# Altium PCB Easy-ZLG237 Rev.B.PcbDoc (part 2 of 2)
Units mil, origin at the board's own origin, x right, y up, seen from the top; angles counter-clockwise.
Board outline 3937.01 x 2559.06 mil, 2 copper layers (Top Layer, Bottom Layer); 111 components, 102 nets, 447 pads, 498 vias.
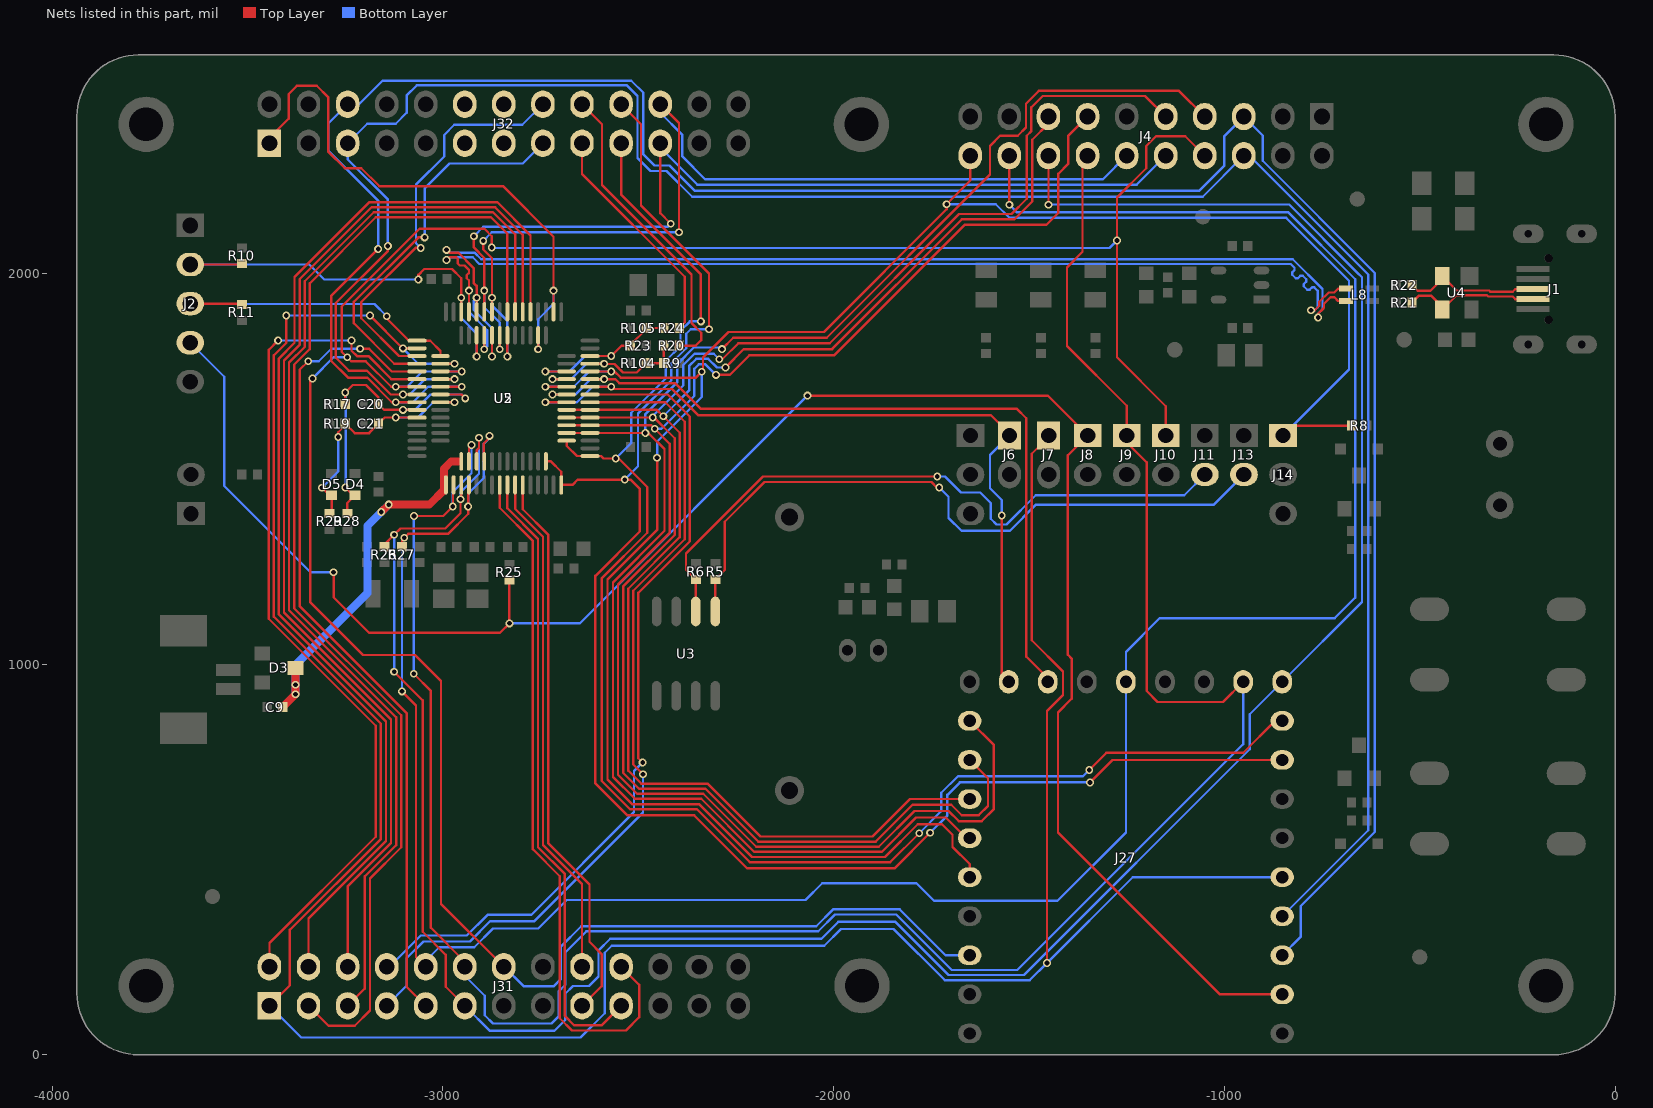
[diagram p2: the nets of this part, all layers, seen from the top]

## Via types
v1: diameter 20, hole 12, Top Layer to Bottom Layer, tented both sides, 498 vias

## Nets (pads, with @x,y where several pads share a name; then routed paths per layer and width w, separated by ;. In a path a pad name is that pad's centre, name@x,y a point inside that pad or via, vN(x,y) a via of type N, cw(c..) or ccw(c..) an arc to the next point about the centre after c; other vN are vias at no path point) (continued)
PA15_1: J7.1 J27.5 J31.1 U2.38 U5.50 | length 6978.5
  Top Layer w6: J31.1@-3444.17,125.15 -3392,177.32 -3392,319.54 -3159,552.54 -3159,847.38 -3433,1121.38 -3433,1790 -3401,1822 v1(-3401,1892) ; v1(-3187,1892) -3102.95,1807.95 U5.50@-3066.46,1807.95 ; U2.38@-3006.42,1768.58 v1(-2970.43,1768.58) ; v1(-1454,235) -1454,880 -1413,921 -1413,981 -1493,1061 -1493,1538 -1450,1581 J7.1@-1450,1585
  Bottom Layer w6: J31.1@-3444.17,125.15 -3363.01,44 -2648,44 -2586,106 -2586,261 -2568,279 -2024,279 -1981,322 -1847,322 -1716,191 -1498,191 v1(-1454,235) -1234.52,454.48 J27.5@-852,454.48 ; v1(-3401,1892) v1(-3187,1892) ; v1(-3102.45,1807.95) -3063.08,1768.58 v1(-2970.43,1768.58)
PB0/ADC12_8_1: J6.1 J27.17 U2.18 U5.26 | length 2037.9
  Top Layer w6: v1(-2737.89,1670.15) U2.18@-2683.58,1670.15 ; U5.26@-2623.54,1709.53 v1(-2569.23,1709.53) -2563.7,1704 -2414,1704 -2347,1637 -1598,1637 -1550,1589 J6.1@-1550,1585 ; v1(-1570,1380) -1570,972.48 J27.17@-1552,954.48
  Bottom Layer w6: v1(-2737.89,1670.15) -2656.85,1670.15 -2617.47,1709.53 v1(-2569.23,1709.53) ; v1(-1570,1380) -1570,1420 -1600,1450 -1600,1535 J6.1@-1550,1585
PB1/ADC12_9_1: J27.16 U2.19 U5.27 | length 2039.7
  Top Layer w6: v1(-2719.57,1689.84) U2.19@-2683.58,1689.84 ; U5.27@-2623.54,1729.21 v1(-2587.55,1729.21) -2559.21,1729.21 -2549,1719 -2406,1719 -2340,1653 -1531,1653 -1507,1629 -1507,1019 -1452,964 J27.16@-1452,954.48
  Bottom Layer w6: v1(-2719.57,1689.84) -2661.16,1689.84 -2621.79,1729.21 v1(-2587.55,1729.21)
PB2_1: J4.20 J14.1 J27.23 R8.2 U2.20 U5.28 | length 5563.1
  Top Layer w6: v1(-2737.89,1709.52) U2.20@-2683.59,1709.52 ; U5.28@-2623.54,1748.9 v1(-2569.23,1748.9) -2560.9,1748.9 -2545,1733 -2352.5,1733 v1(-2337.5,1748) -2334.5,1751 -2334.5,1784.5 -2269,1850 -2025,1850 -1711,2164 v1(-1711,2177) -1650.3,2237.7 J4.20@-1650.3,2301.23 ; v1(-2452,1528) -2452,1343 -2579,1216 -2579,704.23 -2516.29,641.52 -2344.74,641.52 -2209.22,506 -1869,506 -1785,590 -1723,590 -1696,563 -1696,532 -1652,488 J27.23@-1652,454.48 ; J14.1@-850,1585 -825,1610 R8.2@-675,1610
  Bottom Layer w6: v1(-2737.89,1709.52) -2665.48,1709.52 -2626.1,1748.9 v1(-2569.23,1748.9) ; v1(-2452,1528) -2452,1569 -2337.5,1683.5 v1(-2337.5,1748) ; v1(-1711,2177) -1585,2177 -1550,2142 -842,2142 -681,1981 -681,1754 J14.1@-850,1585
PB3_1: J4.8 J10.1 J27.25 J31.14 U2.39 U5.55 | length 7000.3
  Top Layer w6: v1(-3334,1731) -3340,1725 -3340,1158.38 -3204.62,1023 -3071.62,1023 -3005,956.38 -3005,385.99 J31.14@-2844.17,225.15 ; U5.55@-3066.46,1709.53 v1(-3120.77,1709.53) -3132.53,1709.53 -3198,1775 -3235,1775 v1(-3245,1785) -3259,1799 -3259,1915 -3060,2114 -2894,2114 -2875,2095 v1(-2875,2066) ; U2.39@-3006.42,1748.89 v1(-2952.11,1748.89) ; J10.1@-1150,1585 -1150,1660 -1275,1785 v1(-1275,2083.84) -1275,2194 -1200,2269 -1200,2326 -1175,2351 -1100.07,2351 J4.8@-1050.3,2301.23
  Bottom Layer w6: v1(-3334,1731) -3280,1785 v1(-3245,1785) ; v1(-3120.77,1709.53) -3092.47,1709.53 -3053.11,1748.89 v1(-2952.11,1748.89) ; v1(-2875,2066) -2873.84,2064.84 -1294,2064.84 v1(-1275,2083.84) ; J31.14@-2847,229 -2793,175 -2717,175 -2699,193 -2699,276 -2646,329 -2044.71,329 -2001.71,372 -1831,372 -1713.48,254.48 J27.25@-1652,254.48
PB4_1: J4.6 J27.4 J32.5 U2.40 U5.56 | length 5894.4
  Top Layer w6: v1(-3141,2070) -3141,2057 -3274.25,1923.75 -3274.25,1784.25 -3241,1751 -3195,1751 -3133.84,1689.84 v1(-3102.45,1689.84) U5.56@-3066.46,1689.84 ; U2.40@-3006.42,1729.21 v1(-2970.43,1729.21)
  Bottom Layer w6: v1@-3142,2067 v1@-3142,2070 ; v1(-3141,2070) -3141,2189 -3244.17,2292.17 J32.5@-3244.17,2332.87 -3194.04,2383 -3121,2383 -3093,2411 -3093,2455 -3067,2481 -2529,2481 -2502,2454 -2502,2295 -2469,2262 -2428,2262 -2362,2196 -1055.53,2196 J4.6@-950.3,2301.23 -936.44,2301.23 -632,1996.79 -632,574.49 J27.4@-852,354.48 ; v1(-3102.45,1689.84) -3085.16,1689.84 -3045.79,1729.21 v1(-2970.43,1729.21)
PB5_1: J4.5 J27.3 J32.6 U2.41 U5.57 | length 6318.1
  Top Layer w6: v1(-3166,2062) -3286.27,1941.73 -3286.27,1776.27 -3243,1733 -3194,1733 -3131.16,1670.16 v1(-3120.77,1670.16) U5.57@-3066.46,1670.16 ; U2.41@-3006.42,1709.52 v1(-2952.11,1709.52)
  Bottom Layer w6: v1(-3166,2062) -3166,2186 -3294,2314 -3294,2383.04 J32.6@-3244.17,2432.87 -3215.13,2432.87 -3155,2493 -2518,2493 -2487,2462 -2487,2304 -2459,2276 -2420,2276 -2355,2211 -1065,2211 -1000,2276 -1000,2351.53 J4.5@-950.3,2401.23 -902,2352.93 -902,2288 -615,2001 -615,570 -805,380 -805,301.49 J27.3@-852,254.48 ; v1(-3120.77,1670.16) -3076.84,1670.16 -3037.48,1709.52 v1(-2952.11,1709.52)
PB6_7: C20.1 D4.2 R17.1 R28.1 U2.42 U5.58 | length 837.4
  Top Layer w6: v1(-3250,1452) -3230.05,1432.05 D4.2@-3225,1432.05 -3245,1412.05 R28.1@-3245,1385 ; R17.1@-3250,1665 v1(-3250,1695) -3231,1714 -3197,1714 -3165,1682 C20.1@-3165,1665 -3150.47,1650.47 v1(-3102.45,1650.47) U5.58@-3066.46,1650.47 ; U2.42@-3006.42,1689.84 -2952.84,1689.84 v1(-2943,1680)
  Bottom Layer w6: v1(-3250,1452) -3249,1453 -3249,1694 v1(-3250,1695) ; v1(-3102.45,1650.47) -3071.53,1650.47 -3032.16,1689.84 -2952.84,1689.84 v1(-2943,1680)
PB7_7: C21.1 D5.2 R19.1 R29.1 U2.43 U5.59 | length 683.4
  Top Layer w6: v1(-3310,1451) -3291.05,1432.05 D5.2@-3285,1432.05 -3285,1390 R29.1@-3290,1385 ; v1(-3268,1581) -3268,1593 -3250,1611 R19.1@-3250,1615 -3226,1591 -3189,1591 C21.1@-3165,1615 -3149.21,1630.79 v1(-3120.77,1630.79) U5.59@-3066.46,1630.79 ; U2.43@-3006.42,1670.15 v1(-2970.43,1670.15)
  Bottom Layer w6: v1(-3310,1451) -3268,1493 v1(-3268,1581) ; v1(-3120.77,1630.79) -3064.21,1630.79 -3024.85,1670.15 v1(-2970.43,1670.15)
PB10/I2C2_SCL/UART3_TX: R9.1 R20.1 R104.1 U2.21 U5.29 | length 437.2
  Top Layer w6: v1(-2719.57,1729.21) U2.21@-2683.59,1729.21 ; U5.29@-2623.54,1768.58 v1(-2587.55,1768.58) -2586.86,1767.9 -2561.36,1767.9 -2539.46,1746 -2504,1746 R104.1@-2480,1770 R9.1@-2435,1770 R20.1@-2435,1815
  Bottom Layer w6: v1(-2719.57,1729.21) -2671.79,1729.21 -2632.42,1768.58 v1(-2587.55,1768.58)
PB11/I2C2_SDA/UART3_RX: R23.1 R24.1 R105.1 U2.22 U5.30 | length 460.5
  Top Layer w6: v1(-2737.89,1748.89) U2.22@-2683.58,1748.89 ; U5.30@-2623.54,1788.27 v1(-2569.23,1788.27) -2542.5,1815 R23.1@-2520,1815 -2520,1817 -2480,1857 R105.1@-2480,1860 R24.1@-2435,1860
  Bottom Layer w6: v1(-2737.89,1748.89) -2676.11,1748.89 -2636.73,1788.27 v1(-2569.23,1788.27)
PB13/SPI2_SCK: J32.1 U2.26 U5.34 | length 1469.5
  Top Layer w6: J32.1@-3444.17,2332.87 -3444.17,2346.83 -3395,2396 -3395,2459 -3374,2480 -3323,2480 -3294,2451 -3294,2312 -3251,2269 -3209,2269 -3163.27,2223.27 -2846.63,2223.27 -2717.05,2093.69 v1(-2717.05,1955.77) U5.34@-2717.05,1901.46 ; v1(-2756.42,1805.42) U2.26@-2756.42,1841.41
  Bottom Layer w6: v1(-2756.42,1805.42) -2756.42,1882.58 -2717.05,1921.95 v1(-2717.05,1955.77)
PC0/ADC12_10_1: J31.20 U5.8 | length 1807
  Top Layer w6: U5.8@-2854.84,1458.54 -2854.84,1399.84 -2770,1315 -2770,525.85 -2701,456.85 -2701,93.62 -2669.54,62.15 -2531.85,62.15 -2498,96 -2498,178.99 J31.20@-2544.17,225.15
PC1/ADC12_11_1: J31.19 U5.9 | length 1594.9
  Top Layer w6: U5.9@-2835.16,1458.54 -2835.16,1398.54 -2757,1320.38 -2757,531.23 -2688,462.23 -2688,99 -2664.15,75.15 -2594.17,75.15 J31.19@-2544.17,125.15
PC2/ADC12_12_1: J31.18 U5.10 | length 1304.3
  Top Layer w6: U5.10@-2815.47,1458.54 -2815.47,1397.24 -2744,1325.77 -2744,536.62 -2644.17,436.78 J31.18@-2644.17,225.15
PC3/ADC12_13_1: J31.17 U5.11 | length 1437.8
  Top Layer w6: U5.11@-2795.79,1458.54 -2795.79,1395.94 -2731,1331.15 -2731,542 -2625,436 -2625,289 -2594,258 -2594,175.32 J31.17@-2644.17,125.15
PC4/ADC12_14_1: J31.7 U5.24 | length 2230.9
  Top Layer w6: U5.24@-2623.54,1670.16 -2431.16,1670.16 -2381,1620 -2381,1319.38 -2513,1187.38 -2513,743 v1(-2488,718)
  Bottom Layer w6: J31.7@-3144.17,125.15 -3093,176.32 -3093,247 -3050,290 -2931,290 -2879,342 -2766,342 -2488,620 v1(-2488,718)
PC5/ADC12_15_1: J31.8 U5.25 | length 2156.6
  Top Layer w6: U5.25@-2623.54,1689.84 -2424.84,1689.84 -2368,1633 -2368,1314 -2500,1182 -2500,759 v1(-2489,748)
  Bottom Layer w6: J31.8@-3144.17,225.15 -3136.85,225.15 -3057,305 -2939,305 -2886,358 -2774,358 -2511,621 -2511,726 v1(-2489,748)
PC6/PWM_1: J31.4 U5.37 | length 2891.7
  Top Layer w6: J31.4@-3344.17,225.15 -3344.17,348.99 -3146,547.15 -3146,852.77 -3420,1126.77 -3420,1782.15 -3380,1822.15 -3380,1990.34 -3188.07,2182.27 -2861.24,2182.27 -2776.11,2097.14 U5.37@-2776.1,1901.46
PC7/PWM_1: J31.6 U5.38 | length 2809.8
  Top Layer w6: J31.6@-3244.17,225.15 -3244.17,430.6 -3133,541.77 -3133,858.15 -3407,1132.15 -3407,1776.77 -3367,1816.77 -3367,1984.96 -3182.69,2169.27 -2866.63,2169.27 -2795.8,2098.44 U5.38@-2795.79,1901.46
PC8/PWM_1: J31.5 U5.39 | length 2869.3
  Top Layer w6: J31.5@-3244.17,125.15 -3200,169.32 -3200,456.38 -3120,536.38 -3120,863.54 -3394,1137.54 -3394,1771.38 -3354,1811.38 -3354,1979.57 -3177.3,2156.27 -2872.01,2156.27 -2815.48,2099.74 U5.39@-2815.48,1901.45
PC9/PWM_1: J31.3 U5.40 | length 3011.9
  Top Layer w6: J31.3@-3344.17,125.15 -3293.01,74 -3226,74 -3187,113 -3187,451 -3107,531 -3107,868.92 -3381,1142.92 -3381,1766 -3341,1806 -3341,1974.19 -3171.92,2143.27 -2877.27,2143.27 -2835.17,2101.17 U5.40@-2835.16,1901.46
PC10/UART3_TX_1: J32.16 U5.51 | length 1042.7
  Top Layer w6: U5.51@-3066.46,1788.27 -3112.27,1788.27 -3209,1885 -3209,1926.41 -3070.41,2065 v1(-3057,2065)
  Bottom Layer w6: v1(-3057,2065) -3069,2077 -3069,2227 -2997,2299 -2997,2354 -2971,2380 -2797.04,2380 J32.16@-2744.17,2432.87
PC11/UART3_RX_1: J32.15 U5.52 | length 984.6
  Top Layer w6: U5.52@-3066.46,1768.58 -3124.58,1768.58 -3228,1872 -3228,1927 -3063,2092 v1(-3047,2092)
  Bottom Layer w6: v1(-3047,2092) -3047,2217 -2983,2281 -2796.04,2281 J32.15@-2744.17,2332.87
PC12_1: J31.9 U5.53 | length 2108.5
  Top Layer w6: v1(-3345,1775) -3367,1753 -3367,1148.72 -3093,874.72 -3093,173.99 J31.9@-3044.17,125.15 ; v1(-3212,1807) -3189,1807 -3130.9,1748.9 U5.53@-3066.46,1748.9
  Bottom Layer w6: v1(-3345,1775) -3318,1775 -3286,1807 v1(-3212,1807)
PC13_1: J4.14 J9.1 J27.11 J31.12 U2.2 U5.2 | length 6106.5
  Top Layer w6: v1(-3075.01,975.01) -3031,931 -3031,325 -2944.17,238.17 J31.12@-2944.17,225.15 ; v1(-3074,1379) -2999.18,1379 v1(-2974.95,1403.23) -2974.27,1403.92 -2974.27,1457.23 U5.2@-2972.95,1458.54 ; U2.2@-2933.59,1518.58 -2933.59,1553.81 v1(-2926.9,1560.5) ; J4.14@-1350.3,2301.23 -1363,2288.53 -1363,2055 -1403,2015 -1403,1814 -1250,1661 J9.1@-1250,1585 -1250,1567 -1199,1516 -1199,931 -1171,903 -1003.49,903 J27.11@-952,954.48
  Bottom Layer w6: v1(-3075.01,975.01) -3075.01,1377.99 v1(-3074,1379) ; v1(-2974.95,1403.23) -2974.95,1440.05 -2926.9,1488.1 v1(-2926.9,1560.5) ; J31.12@-2944.17,225.15 -2944.17,202.17 -2893,151 -2893,101 -2872,80 -2722,80 -2704,98 -2704,162 -2687,179 -2687,262 -2633,316 -2039.33,316 -1996.33,359 -1840,359 -1698,217 -1530,217 -952,795 J27.11@-952,954.48
PC14_1: J4.16 J27.10 J31.11 R26.1 U2.3 U5.3 | length 6686.2
  Top Layer w6: R26.1@-3150,1300 -3150,1306 v1(-3125,1331) -3109,1347 -2994,1347 -2955.27,1385.73 v1(-2955.27,1421.55) -2953.27,1423.55 U5.3@-2953.27,1458.54 ; v1(-3125,980) -3052,907 -3052,314.6 -2993,255.6 -2993,173.99 J31.11@-2944.17,125.15 ; U2.3@-2913.9,1518.58 -2913.9,1546.63 -2907.9,1552.63 -2907.9,1578.9 v1(-2908,1579) ; v1(-1450.3,2175.3) J4.16@-1450.3,2301.23
  Bottom Layer w6: v1(-3125,980) v1(-3125,1331) ; v1(-2955.27,1421.55) -2955.27,1439.73 -2907.9,1487.1 -2907.9,1578.9 v1(-2908,1579) ; J31.11@-2944.17,125.15 -2880.01,61 -2715,61 -2687,89 -2687,156 -2667,176 -2626,176 -2602,200 -2602,267 -2572,297 -2031.46,297 -1988.46,340 -1842,340 -1706,204 -1513,204 -935,782 -935,871.49 J27.10@-852,954.48 -648,1158.49 -648,1990 -659,2001 -834,2176 -1394.44,2176 -1449.6,2176 v1(-1450.3,2175.3)
PC15_1: J4.18 J27.14 J31.10 R27.1 U2.4 U5.4 | length 6682.8
  Top Layer w6: v1(-3105,930) -3069,894 -3069,249.99 J31.10@-3044.17,225.15 ; R27.1@-3105,1300 -3105,1317 v1(-3099,1323) -3089,1333 -2987,1333 -2935.58,1384.42 v1(-2935.58,1403.23) -2934.9,1403.92 -2934.9,1457.23 U5.4@-2933.58,1458.54 ; U2.4@-2894.22,1518.58 -2895.9,1520.26 -2895.9,1564.23 -2881,1579.13 v1(-2881,1584) ; v1(-1550.3,2175.3) J4.18@-1550.3,2301.23
  Bottom Layer w6: v1(-3105,930) -3105,1317 v1(-3099,1323) ; J31.10@-3044.17,225.15 -3044.17,240.15 -3009.32,275 -2920,275 -2872,323 -2756,323 -2683,396 -2072.46,396 -2029.46,439 -1788,439 -1743,394 -1427,394 -1252,569 J27.14@-1252,954.48 -1252,1031 -1166,1117 -718,1117 -665,1170 -665,1985 -836,2156 -1395,2156 -1531,2156 v1(-1550.3,2175.3) ; v1(-2935.58,1403.23) -2935.58,1436.42 -2895.53,1476.47 -2895.53,1563.4 -2881,1577.94 v1(-2881,1584)
PD2/PWM_1: J31.2 U5.54 | length 2250.7
  Top Layer w6: J31.2@-3444.17,225.15 -3444.17,285.76 -3172,557.92 -3172,842 -3446,1116 -3446,1804 v1(-3422,1828) ; v1(-3234,1828) -3234,1802 -3220,1788 -3191,1788 -3132.21,1729.21 U5.54@-3066.46,1729.21
  Bottom Layer w6: v1(-3422,1828) v1(-3234,1828)
RST: J2.4 J8.1 J27.2 R25.1 | length 5012
  Top Layer w6: v1(-3280,1235) -3280,1171 -3189,1080 -2854,1080 v1(-2830,1104) R25.1@-2830,1215 ; v1(-2067,1687) -1452,1687 J8.1@-1350,1585 -1401,1534 -1401,1024 -1391,1014 -1391,911 -1426,876 -1426,569 -1011.48,154.48 J27.2@-852,154.48
  Bottom Layer w6: J2.4@-3647.05,1822.54 -3560,1735.48 -3560,1456 -3339,1235 v1(-3280,1235) ; v1(-2830,1104) -2650,1104 v1(-2067,1687)
SCL_3: J11.2 R6.1 U3.2 | length 1695.8
  Top Layer w6: U3.2@-2353.01,1134.52 R6.1@-2353.01,1216.48 -2378,1241.48 -2378,1283 -2181,1480 v1(-1735,1480)
  Bottom Layer w6: v1(-1735,1480) -1715,1480 -1674,1439 -1625,1439 -1598,1412 -1598,1372 -1583,1357 -1558,1357 -1483,1432 -1103,1432 J11.2@-1050,1485
SDA_3: J13.2 R5.1 U3.1 | length 1753.7
  Top Layer w6: U3.1@-2303.01,1134.52 R5.1@-2303.01,1216.48 -2279,1240.49 -2279,1364 -2177,1466 -1750,1466 -1736,1452 v1(-1730,1452)
  Bottom Layer w6: v1(-1730,1452) -1706,1428 -1706,1374 -1673,1341 -1549,1341 -1482,1408 -1027,1408 J13.2@-950,1485
SPI1_MISO_1: J4.9 J27.20 U2.16 U5.22 | length 4263.7
  Top Layer w6: U2.16@-2683.59,1630.78 U5.22@-2623.54,1630.79 v1(-2463,1630.79) -2459.79,1630.79 -2407,1578 -2407,1330.15 -2539,1198.15 -2539,721.84 -2498.16,681 -2328.38,681 -2192.87,545.48 -1892.52,545.48 -1798,640 -1699,640 -1672,613 -1629,613 -1605,637 -1605,707.48 J27.20@-1652,754.48 ; v1(-2293,1780) -2285,1780 -2244,1821 -2010,1821 -1679,2152 -1545,2152 -1506,2191 -1506,2352 -1494,2364 -1494,2425 -1465,2454 -1203.07,2454 J4.9@-1150.3,2401.23
  Bottom Layer w6: v1(-2463,1630.79) -2463,1635 -2385,1713 -2385,1765 -2356,1794 -2307,1794 v1(-2293,1780)
SPI1_MOSI_1: J4.15 J27.21 U2.17 U5.23 | length 3678.4
  Top Layer w6: U2.17@-2683.59,1650.47 U5.23@-2623.54,1650.47 -2452.47,1650.47 v1(-2436,1634) -2394,1592 -2394,1324.77 -2526,1192.77 -2526,727.23 -2492.77,694 -2323,694 -2187.48,558.48 -1900.52,558.48 -1804.52,654.48 J27.21@-1652,654.48 ; v1(-2277,1759) -2230,1806 -2004,1806 -1672,2138 -1538,2138 -1492,2184 -1492,2342 -1450.3,2383.7 J4.15@-1450.3,2401.23
  Bottom Layer w6: v1(-2436,1634) -2370,1700 -2370,1763 -2352,1781 -2321,1781 -2299,1759 v1(-2277,1759)
SPI1_NSS_1: J4.7 J27.22 U2.14 U5.20 | length 4170.5
  Top Layer w6: U2.14@-2683.59,1591.41 U5.20@-2623.54,1591.42 v1(-2482,1591.42) -2474.42,1591.42 -2433,1550 -2433,1340.92 -2565,1208.92 -2565,711.07 -2508.93,655 -2339.15,655 -2203.64,519.48 -1876.52,519.48 -1789,607 -1713,607 -1660.48,554.48 J27.22@-1652,554.48 ; v1(-2286,1806) -2257,1835 -2018,1835 -1600,2253 -1600,2326 -1574,2352 -1529,2352 -1508,2373 -1508,2434 -1475,2467 -1116.07,2467 J4.7@-1050.3,2401.23
  Bottom Layer w6: v1(-2482,1591.42) -2482,1640 -2400,1722 -2400,1768 -2358,1810 -2290,1810 v1(-2286,1806)
SPI1_SCK_1: J4.13 J27.19 U2.15 U5.21 | length 4138.4
  Top Layer w6: U2.15@-2683.59,1611.1 U5.21@-2623.54,1611.1 -2467.1,1611.1 v1(-2458,1602) -2420,1564 -2420,1335.54 -2552,1203.54 -2552,716.46 -2503.54,668 -2333.77,668 -2198.25,532.48 -1884.51,532.48 -1793,624 -1706,624 -1680,598 -1621,598 -1590,629 -1590,792.48 J27.19@-1652,854.48 ; v1(-2301,1740) -2266,1740 -2216,1790 -1999,1790 -1665,2124 -1456,2124 -1425,2155 -1425,2255 -1400,2280 -1400,2351.53 J4.13@-1350.3,2401.23
  Bottom Layer w6: v1(-2458,1602) -2441,1602 -2357,1686 -2357,1755.37 -2345.37,1767 -2328,1767 v1(-2301,1740)
SWCLK/PA14_7: J2.3 R11.2 U2.37 U5.49 | length 839.1
  Top Layer w6: J2.3@-3647.05,1922.54 -3517.54,1922.54 R11.2@-3515,1920 ; v1@-3145.5,1886.5 -3086.64,1827.64 U5.49@-3066.46,1827.64 -3032.64,1827.64 -3006.42,1801.42 U2.37@-3006.42,1788.26 ; v1@-3144,1888 v1(-3144,1890)
  Bottom Layer w6: J2.3@-3647.05,1922.54 -3645.79,1921.27 -3175.27,1921.27 v1(-3144,1890)
SWDIO/PA13_7: J2.2 R10.1 U2.34 U5.46 | length 1177.6
  Top Layer w6: J2.2@-3647.05,2022.54 -3517.46,2022.54 R10.1@-3515,2025 ; v1(-3063,1984) -3063,1996 -3048,2011 -2977,2011 -2953.27,1987.27 v1(-2953.27,1937.45) U5.46@-2953.27,1901.46 ; v1(-2913.9,1787.1) U2.34@-2913.9,1841.41
  Bottom Layer w6: J2.2@-3647.05,2022.54 -3342.54,2022.54 -3304,1984 v1(-3063,1984) ; v1(-2953.27,1937.45) -2953.27,1885.27 -2913.9,1845.9 v1(-2913.9,1787.1)
UART1_RX_1: J4.10 J32.21 U2.31 U5.43 | length 2516.4
  Top Layer w6: v1(-2921,2095) -2921,2066 -2894.21,2039.21 v1(-2894.21,1955.77) U5.43@-2894.21,1901.46 ; v1(-2854.85,1805.42) U2.31@-2854.85,1841.41 ; J32.21@-2444.17,2332.87 -2444.17,2154.17 v1(-2417,2127)
  Bottom Layer w6: v1(-2921,2095) -2897,2119 -2425,2119 v1(-2417,2127) ; v1(-2894.21,1955.77) -2894.21,1913.21 -2854.85,1873.85 v1(-2854.85,1805.42) ; J32.21@-2444.17,2332.87 -2444.17,2322.17 -2349,2227 -1224.53,2227 J4.10@-1150.3,2301.23
UART1_TX_1: J4.12 J32.22 U2.30 U5.42 | length 2613
  Top Layer w6: v1(-2897,2083) -2897,2061 -2874.53,2038.53 v1(-2874.53,1937.45) U5.42@-2874.53,1901.46 ; v1(-2835.16,1787.1) U2.30@-2835.16,1841.41 ; J32.22@-2444.17,2432.87 -2396,2384.7 v1(-2396,2105)
  Bottom Layer w6: v1(-2897,2083) -2875,2105 v1(-2396,2105) ; v1(-2874.53,1937.45) -2874.53,1917.53 -2835.16,1878.16 v1(-2835.16,1787.1) ; J32.22@-2444.17,2432.87 -2444.17,2411.17 -2388,2355 -2388,2300 -2329,2241 -1310.53,2241 J4.12@-1250.3,2301.23
UART2_RX_1: J27.9 J32.19 U2.13 U5.17 | length 4067.4
  Top Layer w6: U2.13@-2683.59,1571.73 -2683.58,1558.58 -2657.36,1532.36 U5.17@-2623.54,1532.36 -2595.36,1532.36 -2589,1526 v1(-2558,1526) -2550,1526 -2477,1453 -2477,1336 -2594,1219 -2594,701.23 -2521.29,628.52 -2350.12,628.52 -2214.61,493 -1855,493 v1(-1781,567) ; J32.19@-2544.17,2332.87 -2544.17,2201.46 -2340,1997.3 v1(-2340,1877) ; v1(-1346,729) -1302,773 -952,773 -870.52,854.48 J27.9@-852,854.48
  Bottom Layer w6: v1(-2558,1526) -2518,1566 -2518,1643 -2430,1731 -2430,1776 -2392,1814 -2392,1853 -2368,1877 v1(-2340,1877) ; v1(-1781,567) -1724.5,623.5 -1724.5,670.5 -1682,713 -1362,713 v1(-1346,729)
UART2_TX_1: J27.8 J32.20 U2.12 U5.16 | length 4266.7
  Top Layer w6: U2.12@-2736.74,1518.58 -2723.58,1518.58 -2697.36,1492.36 U5.16@-2697.36,1458.54 -2668.46,1458.54 -2655,1472 v1(-2535,1472) -2520,1472 -2496,1448 -2496,1339.63 -2610,1225.63 -2610,694.6 -2527.92,612.52 -2356.75,612.52 -2221.24,477 -1844.13,477 v1(-1753.13,568) ; J32.20@-2544.17,2432.87 -2493,2381.7 -2493,2173.3 -2319,1999.3 v1(-2319,1857) ; v1(-1344,697) -1286.52,754.48 J27.8@-852,754.48
  Bottom Layer w6: v1(-2535,1472) -2501,1506 -2501,1641 -2416,1726 -2416,1769.6 -2377.6,1808 -2377.6,1845.27 -2365.87,1857 v1(-2319,1857) ; v1(-1753.13,568) -1709,612.13 -1709,665 -1677,697 v1(-1344,697)
UART3_RX_1: J32.17 R24.2 | length 587.7
  Top Layer w6: J32.17@-2644.17,2332.87 -2644.17,2254.17 -2381,1991 -2381,1874 R24.2@-2395,1860
UART3_TX_1: J32.18 R20.2 | length 792.1
  Top Layer w6: J32.18@-2644.17,2432.87 -2593,2381.7 -2593,2226.3 -2364,1997.3 -2364,1873 -2339,1848 -2339,1829 -2353,1815 R20.2@-2395,1815
UART4_RX_AWORKS: J32.13
UART4_TX_AWORKS: J32.14
UART5_RX_AWORKS: J32.11
UART5_TX_AWORKS: J32.12
USB_1_N: L8.1 U2.32 U5.44 | length 2901.1
  Top Layer w6: v1(-2991,2060) -2984,2053 -2961,2053 -2921.58,2013.58 -2921.58,1975.58 -2913.9,1967.9 v1(-2913.9,1937.45) U5.44@-2913.9,1901.46 ; v1(-2874.53,1787.1) U2.32@-2874.53,1841.41 ; v1(-760.05,1887.05) -760.05,1896.95 -748,1909 -745,1912 -745,1922.03 -728.03,1939 -718.93,1939 -709.18,1929.25 L8.1@-688.46,1929.25
  Bottom Layer w6: v1(-2991,2060) -2984,2053 -2919,2053 -2902,2036 -825,2036 -749,1960 -749,1908 -760.05,1896.95 v1(-760.05,1887.05) ; v1(-2913.9,1937.45) -2921.58,1929.77 -2921.58,1906.52 -2874.53,1859.48 v1(-2874.53,1787.1)
USB_1_P: L8.4 U2.33 U5.45 | length 2899.6
  Top Layer w6: v1(-2991,2034) -2984,2041 -2965.97,2041 -2961.97,2037 -2961.97,2024.97 -2957,2020 -2944.97,2020 -2933.58,2008.61 -2933.58,2001 -2939,1995.58 -2939,1987.61 -2933.58,1982.19 v1(-2933.58,1955.77) U5.45@-2933.58,1901.46 ; v1(-2894.22,1805.42) U2.33@-2894.22,1841.41 ; v1(-778.43,1905.44) -768.54,1905.44 -757,1916.97 -757,1927 -733,1951 -718.93,1951 -709.18,1960.75 L8.4@-688.46,1960.75
  Bottom Layer w6: v1(-2991,2034) -2984,2041 -2923.97,2041 -2906.97,2024 -829.97,2024 -820.43,2014.46 -820.43,2008.52 -826.51,2002.44 -826.51,1996.5 -817.6,1987.59 -811.66,1987.59 -805.58,1993.67 -799.64,1993.67 -790.73,1984.76 -790.73,1978.82 -796.81,1972.74 -796.81,1966.8 -787.9,1957.89 -781.96,1957.89 -775.88,1963.97 -769.94,1963.97 -761,1955.03 -761,1912.97 -768.54,1905.44 v1(-778.43,1905.44) ; v1(-2933.58,1955.77) -2933.58,1901.55 -2886.53,1854.5 -2886.53,1813.1 v1(-2894.22,1805.42)
USB_DEVICE1_6_N: J1.2 R21.2 U4.3 | length 356.2
  Top Layer w6: R21.2@-520,1925 -502,1943 -471,1943 -445.5,1917.5 -445.5,1910 U4.3@-442.5,1907 -405.5,1944 -327.97,1944 -324.71,1940.74 -262.17,1940.74 -255.38,1933.95 J1.2@-210.06,1933.95
USB_DEVICE1_6_P: J1.3 R22.1 U4.2 | length 355.8
  Top Layer w6: R22.1@-520,1970 -505,1955 -473,1955 -445.5,1982.5 -445.5,1990 U4.2@-442.5,1993 -405.5,1956 -323,1956 -319.74,1952.74 -262.17,1952.74 -255.38,1959.54 J1.3@-210.06,1959.54
VBAT: C9.1 D3.3 U2.1 U5.1 | length 982.9
  Top Layer w20: C9.1@-3410,890 v1(-3377.5,922.5) v1(-3377.5,947) D3.3@-3377.5,990 ; v1(-3158,1389) v1(-3139,1408) -3035,1408 -2997.6,1445.4 -2997.6,1499.9 -2978.92,1518.58 -2958.45,1518.58
  Bottom Layer w20: v1(-3377.5,922.5) v1(-3377.5,947) -3377.5,997.5 -3193,1182 -3193,1354 v1(-3158,1389) v1(-3139,1408)
pads on no net: HOLE2.1 HOLE3.1 HOLE4.1 HOLE5.1 HOLE6.1 J1.0 J1.4 MARK1.0 MARK2.0 MARK3.0 U3.3

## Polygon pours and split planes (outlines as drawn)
GND on Top Layer "GND_L01_P004" (solid, remove dead copper, pour order 4): 0,2401.58 ccw(c-157.48,2401.58) -157.48,2559.06 -3779.52,2559.06 ccw(c-3779.52,2401.58) -3937,2401.58 -3937.01,2401.58 -3937.01,157.54 ccw(c-3779.53,157.54) -3779.53,0.06 -3779.53,0 -157.48,0 ccw(c-157.48,157.48) 0,157.48
GND on Bottom Layer "GND_L02_P005" (solid, remove dead copper, pour order 5): 0,2401.58 ccw(c-157.48,2401.58) -157.48,2559.06 -3779.52,2559.06 ccw(c-3779.52,2401.58) -3937,2401.58 -3937.01,2401.58 -3937.01,157.54 ccw(c-3779.53,157.54) -3779.53,0.06 -3779.53,0 -157.48,0 ccw(c-157.48,157.48) 0,157.48

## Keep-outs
Keep-Out Layer:
  lines w1: -3937.01,157.54 -3937.01,2401.58 ; -3779.53,0 -157.48,0 ; -3779.52,2559.06 -157.48,2559.06 ; 0,157.48 0,2401.58
  lines w5: -8127.76,0.11 -7952.76,0.11 ; -8127.76,5118.17 -7952.76,5118.17 ; -7952.76,-174.89 -7952.76,0.11 ; -7952.76,157.59 -7952.76,0.11 ; -7952.76,4960.69 -7952.76,5118.17 ; -7795.28,0.11 -7952.76,0.11 ; -7795.28,5118.17 -7952.76,5118.17 ; -3937.01,2401.58 -3937.01,2559.11 -3779.53,2559.11 ; -3937,2401.58 cw(c-3779.52,2401.58) -3779.52,2559.06 ; 0,-175 0,0 ; -3937.01,157.54 ccw(c-3779.53,157.54) -3779.53,0.06 ; -3937.01,157.54 ccw(c-3779.53,157.54) -3779.53,0.06 ; -3937.01,157.54 -3937.01,0.06 -3779.53,0.06 ; 0,0 -157.48,0 ccw(c-157.48,157.48) 0,157.48 0,0 ; -157.48,2559.06 cw(c-157.48,2401.58) 0,2401.58 0,2559.06 -157.48,2559.06

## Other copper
Top Layer:
  rectangle net GND: -555,2075 -470,2284.83
  rectangle net 3.3V: -2553,1939 -2482,1999
  rectangle net 3.3V: -2917,1605 -2764,1757
  rectangle: -2432.69,972.48 -2141.01,1080.48
  rectangle: -2199.01,796.48 -2037.01,1256.48
  region net EARTH: -233.95,2525 -123.42,2525 -25,2426.58 -25,2150 -35,2140 -320,2140 -335,2155 -335,2290 -295,2330 -295,2463.95
  region net GND: -185,2014.08 -204,2033.08 -249,2033.08 -258,2024.08 -258,2014.08
  region net NetJ1_1: -185,1905 -204,1886 -249,1886 -258,1895 -258,1905
  region net 3.3V: -2708.9,1783.29 -2713.5,1787.89 -2676.3,1825.09 -2659.9,1825.09 -2659.9,1785.59 -2662.2,1783.29
  region net 3.3V: -2981.11,1576.7 -2976.51,1572.1 -3013.71,1534.91 -3030.11,1534.9 -3030.11,1574.4 -3027.81,1576.7
  region net 3.3V: -2948.3,1816.1 -2952.9,1811.5 -2990.1,1848.7 -2990.1,1865.1 -2950.6,1865.1 -2948.3,1862.8
Bottom Layer:
  region net EARTH: -233.95,2525 -123.42,2525 -25,2426.58 -25,2150 -35,2140 -320,2140 -335,2155 -335,2290 -295,2330 -295,2463.95
  region net 3.3V: -2519,2000 -2502,1983 -2502,1971 -2532,1941 -2560,1941 -2565,1946 -2565,1994 -2559,2000
  pour cut-out: -1284,2067 -1284,2038 -1292,2038 -1306,2052 -1306,2052.84 -1294,2064.84
Multi-Layer:
  pour cut-out: -470,2300 -450,2320 -390,2320 -350,2360 -350,2540 -335,2555 -115,2555 0,2440 0,1730 -25,1705 -255,1705 -315,1765 -315,1850 -280,1885 -185,1885 -165,1905 -165,2015 -183.08,2033.08 -293.08,2033.08 -295,2035 -420,2035 -470,2085
  pour cut-out: -3759.84,2263.26 cw(c-3759.84,2381.37) -3877.95,2381.37 cw(c-3759.84,2381.37) -3759.84,2499.48 cw(c-3759.84,2381.37) -3641.73,2381.37 cw(c-3759.84,2381.37)
  pour cut-out: -3759.84,58.54 cw(c-3759.84,176.65) -3877.95,176.65 cw(c-3759.84,176.65) -3759.84,294.76 cw(c-3759.84,176.65) -3641.73,176.65 cw(c-3759.84,176.65)
  pour cut-out: -1929.13,2263.26 cw(c-1929.13,2381.37) -2047.24,2381.37 cw(c-1929.13,2381.37) -1929.13,2499.48 cw(c-1929.13,2381.37) -1811.02,2381.37 cw(c-1929.13,2381.37)
  pour cut-out: -1927.56,58.54 cw(c-1927.56,176.65) -2045.67,176.65 cw(c-1927.56,176.65) -1927.56,294.76 cw(c-1927.56,176.65) -1809.45,176.65 cw(c-1927.56,176.65)
  pour cut-out: -177.17,58.54 cw(c-177.17,176.65) -295.28,176.65 cw(c-177.17,176.65) -177.17,294.76 cw(c-177.17,176.65) -59.06,176.65 cw(c-177.17,176.65)
  pour cut-out: -177.17,2263.26 cw(c-177.17,2381.37) -295.28,2381.37 cw(c-177.17,2381.37) -177.17,2499.48 cw(c-177.17,2381.37) -59.06,2381.37 cw(c-177.17,2381.37)

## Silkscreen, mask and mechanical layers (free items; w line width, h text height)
Top Overlay:
  region: -3693.4,-484.6 -3693.4,-496.6 -3838.4,-496.6 -3838.4,-523.6 -3693.4,-523.6 -3693.4,-534.6 -3631.4,-509.6
  lines w8: -3838.4,-523.6 -3693.4,-523.6 -3693.4,-534.6 -3631.4,-509.6 -3693.4,-484.6 -3693.4,-496.6 -3838.4,-496.6 -3838.4,-523.6
  text "DEVICE1" at -215,2150 h30
  text "3.3V" at -3807.01,2134.48 h30
  text "PWR" at -1598,2054 h30 r90
  text "SWDIO" at -3837.01,2034.48 h30
  text "SWCLK" at -3852.01,1934.48 h30
  text "RST" at -3792.01,1834.48 h30
  text "GND" at -3797.01,1734.48 h30
  text "PB0" at -1536,1651 h30 r90
  text "PA15" at -1433,1651 h30 r90
  text "PC13" at -1239,1651 h30 r90
  text "PB3" at -1133,1651 h30 r90
  text "PB6" at -1038,1651 h30 r90
  text "PB7" at -936,1651 h30 r90
  text "5V" at -1770,1570 h30
  text "PB2" at -750,1548 h30 r90
  text "Vmic" at -1815,1475 h30
  text "KEY" at -750,1447 h30 r90
  text "3.3VA" at -1825,1370 h30
  text "BOOT0" at -3716,1364 h30 r90
  text "RES" at -750,1351 h30 r90
  text "RST" at -1334,1341.86 h30 r90
  text "SCL" at -1036,1341.57 h30 r90
  text "SDA" at -934,1339 h30 r90
  text "ADC" at -1534,1337.29 h30 r90
  text "LED1" at -1137,1337.43 h30 r90
  text "LED0" at -1235,1324.57 h30 r90
  text "BEEP" at -1433,1321.43 h30 r90
  text "Easy-ZLG237" at -3144,876 h50
  text "KEY/RES" at -390,875 h30
  text "200107 Rev.B" at -3086.21,792.08 h36
  text "P/N:13.01.04705" at -3122.2,718.48 h36
  text "RST" at -335,465 h30
  text "MicroPort" at -1454.01,437.06 h60
  text "生产用，板厂无需理会，删除即可" at -4408,-525 h40
Bottom Overlay:
  text "PA2" at -2594.17,2455.74 h30 r315
  text "PA9" at -2494.17,2455.74 h30 r315
  text "3.3V" at -2394.17,2455.74 h30 r315
  text "5V" at -2294.17,2455.74 h30 r315
  text "PC10" at -2790,2455 h30 r315
  text "NC" at -3194.17,2452.87 h30 r315
  text "PB9" at -3094.17,2452.87 h30 r315
  text "NC" at -2994.17,2452.87 h30 r315
  text "NC" at -2894.17,2452.87 h30 r315
  text "PB11" at -1665.3,2451.23 h30 r270
  text "PB10" at -1565.3,2451.23 h30 r270
  text "PA7" at -1465.3,2451.23 h30 r270
  text "PA5" at -1365.3,2451.23 h30 r270
  text "PA8" at -1265.3,2451.23 h30 r270
  text "PA6" at -1165.3,2451.23 h30 r270
  text "PA4" at -1065.3,2451.23 h30 r270
  text "PB5" at -965.3,2451.23 h30 r270
  text "GND" at -865.3,2451.23 h30 r270
  text "3.3V" at -765.3,2451.23 h30 r270
  text "PB5" at -3294,2450 h30 r315
  text "PB10" at -2690,2450 h30 r315
  text "PB12" at -3494.17,2442.87 h30 r315
  text "PB15" at -3394.17,2442.87 h30 r315
  text "NC" at -2969.17,2248.85 h30 r315
  text "NC" at -2869.17,2248.85 h30 r315
  text "NC" at -3165,2245 h30 r315
  text "PB8" at -3054.17,2240.14 h30 r315
  text "PB4" at -3254.17,2238.71 h30 r315
  text "PA3" at -2554.17,2237 h30 r315
  text "GND" at -2254.17,2237 h30 r315
  text "GND" at -2350,2235 h30 r315
  text "PB11" at -2650,2230 h30 r315
  text "PC11" at -2745,2225 h30 r315
  text "PB13" at -3454.17,2218.14 h30 r315
  text "PB14" at -3335,2215 h30 r315
  text "PA10" at -2430,2215 h30 r315
  text "5V" at -765.3,2201.08 h30 r270
  text "PB2" at -1665.3,2177.23 h30 r270
  text "PB3" at -1065.3,2177.23 h30 r270
  text "PB4" at -965.3,2175.8 h30 r270
  text "PA9" at -1265.3,2175.52 h30 r270
  text "GND" at -865.3,2174.09 h30 r270
  text "PC15" at -1565.3,2152.09 h30 r270
  text "PC13" at -1365.3,2152.09 h30 r270
  text "PA10" at -1165.3,2152.09 h30 r270
  text "PC14" at -1465.3,2150.67 h30 r270
  text "3.3V" at -3717.01,2104.48 h30
  text "TXD" at -1265,2046 h30 r270
  text "RXD" at -1165,2046 h30 r270
  text "SWDIO" at -3717.01,2004.48 h30
  text "SWCLK" at -3717.01,1904.48 h30
  text "RST" at -3717.01,1804.48 h30
  text "GND" at -3717.01,1704.48 h30
  text "AGND" at -1667,1024.48 h30 r270
  text "PB0" at -1567,1024.48 h30 r270
  text "PB1" at -1467,1024.48 h30 r270
  text "NC" at -1367,1024.48 h30 r270
  text "PC15" at -1267,1024.48 h30 r270
  text "PB7" at -1167,1024.48 h30 r270
  text "PB6" at -1067,1024.48 h30 r270
  text "PC13" at -967,1024.48 h30 r270
  text "PC14" at -867,1024.48 h30 r270
  text "RXD" at -595,840 h30
  text "PA3" at -702,839.48 h30
  text "PA5" at -1727,834.48 h30
  text "TXD" at -592,740 h30
  text "PA2" at -702,739.48 h30
  text "PA6" at -1727,733.95 h30
  text "CTS" at -592,640 h30
  text "PA0" at -702,639.48 h30
  text "PA7" at -1727,633.41 h30
  text "RTS" at -595,540 h30
  text "PA1" at -714.86,539.48 h30
  text "PA4" at -1727,532.88 h30
  text "PA15" at -680.01,439.48 h30
  text "PB2" at -1727,432.34 h30
  text "PB4" at -703.72,339.48 h30
  text "PA8" at -1727,331.81 h30
  text "MIC" at -2490,255 h30 r315
  text "PC13" at -2990,245 h30 r315
  text "PB3" at -2887,245 h30 r315
  text "PB6" at -2790,245 h30 r315
  text "PC0" at -2586,245 h30 r315
  text "PD2" at -3494.17,242.14 h30 r315
  text "HPR" at -2394.17,240.57 h30 r315
  text "PC6" at -3394.17,240.43 h30 r315
  text "PC15" at -3090,240 h30 r315
  text "PC2" at -2688,240 h30 r315
  text "PC7" at -3294.17,239 h30 r315
  text "PC5" at -3194.17,239 h30 r315
  text "GND" at -2294.17,239 h30 r315
  text "PB5" at -705.14,239.48 h30
  text "PB3" at -1727,231.27 h30
  text "RST" at -705.14,139.48 h30
  text "3.3V" at -1727,130.73 h30
  text "GND" at -702,39.48 h30
  text "5V" at -2265,37 h30 r315
  text "5V/3.3VA" at -1727,34.48 h30
  text "PC1" at -2560,30 h30 r315
  text "PC9" at -3350,25 h30 r315
  text "PC4" at -3150,25 h30 r315
  text "PB7" at -2749.17,22.73 h30 r315
  text "PC8" at -3249.17,21.16 h30 r315
  text "PA8" at -2849.17,21.16 h30 r315
  text "PC3" at -2649.17,21.16 h30 r315
  text "GND" at -2450,20 h30 r315
  text "Vref" at -2345,20 h30 r315
  text "PA15" at -3450,15 h30 r315
  text "PC12" at -3040,15 h30 r315
  text "PC14" at -2940,15 h30 r315
Mechanical 1:
  lines w5: -8160,2560 -8005,2560 -8035,2590 ; -7795.28,2559.11 cw(c-7795.28,2716.59) -7952.76,2716.59 -7952.76,4960.69 cw(c-7795.28,4960.69) -7795.28,5118.17 -4173.23,5118.17 ; -4173.23,2559.17 -7795.28,2559.17 ccw(c-7795.28,2401.69) -7952.76,2401.69 -7952.76,157.59 ccw(c-7795.28,157.59) -7795.28,0.11 -4173.23,0.11 ccw(c-4173.24,157.59) -4015.76,157.59 ; -4015.76,157.54 -3937.01,157.54 ; -4015.76,1732.34 -3937.01,1732.34 ; -4015.76,2716.59 cw(c-4173.24,2716.59) -4173.24,2559.11 ; -4015.76,4960.63 -3937.01,4960.63 -3937.01,2716.59 ; -4015.75,157.59 -4015.75,2401.63 ; -4015.75,2716.59 -4015.75,4960.63 ; -4015.75,3385.83 -3937,3385.83 ; -3974.11,5365 -3974.11,5170.36 -3944.11,5200.36 ; -3937.01,2401.58 -3937.01,157.54 ; -3937,2401.58 cw(c-3779.52,2401.58) -3779.52,2559.06 -157.48,2559.06 ; -3937,4960.63 cw(c-3779.52,4960.63) -3779.52,5118.11 -157.48,5118.11 cw(c-157.48,4960.63) 0,4960.63 0,2716.54 cw(c-157.48,2716.54) -157.48,2559.06 ; -3779.53,0 -157.48,0 ccw(c-157.48,157.48) 0,157.48 0,2401.58 ccw(c-157.48,2401.58) -157.48,2559.06 ; -4173.23,2559.11 cw(c-4173.23,2401.63) -4015.75,2401.63 ; -4173.23,2559.11 cw(c-4173.23,2401.63) -4015.75,2401.63 ; -3937.01,157.54 ccw(c-3779.53,157.54) -3779.53,0.06 cw(c-3779.53,157.54) -3937.01,157.54 ; -3937.01,2716.6 ccw(c-3779.53,2716.6) -3779.53,2559.11 cw(c-3779.53,2716.6) -3937.01,2716.6 ; -4173.23,5118.11 cw(c-4173.23,4960.63) -4015.75,4960.63 ccw(c-4173.23,4960.63) -4173.23,5118.11
  text "V-CUT * 2" at -4005,5160 h30 r90
  text "F" at -5920,4404.06 h1000 r180
  text "F" at -2025,3265 h1000
  text "V-CUT" at -8155,2510 h30
  text "F" at -5920,1869.06 h1000 r180
Mechanical 2:
  drawing of 637 lines, arcs and shapes, not listed
  text "PCB加工工艺要求" at 2007.99,4221.48 h280
  text "mm x" at 1204.99,4035.48 h100
  text "mm" at 1814.99,4035.48 h100
  text "202" at 869.99,4026.48 h100
  text "130" at 1479.99,4026.48 h100
  text "IPC-600E   IPC-6011/12" at 2972.99,4025.48 h100
  text "IPC-Ⅱ" at 4307.99,4024.48 h100
  text "IPC-Ⅲ" at 4807.99,4024.48 h100
  text "尺寸" at 316.69,4007.63 h150
  text "验收标准" at 2316.69,4007.63 h150
  text "FR4 TG140" at 1022.99,3825.48 h100
  text "FR4 TG170" at 1922.99,3825.48 h100
  text "生益有胶材料" at 2822.99,3825.48 h100
  text "MEGTRON6" at 3722.99,3825.48 h100
  text "其他：" at 4622.99,3825.48 h100
  text "板材" at 315.26,3807.41 h150
  text "单面" at 1022.99,3625.48 h100
  text "2" at 1722.99,3625.48 h100
  text "4" at 2422.99,3625.48 h100
  text "6" at 3122.99,3625.48 h100
  text "8" at 3822.99,3625.48 h100
  text "10" at 4522.99,3625.48 h100
  text "板层" at 315.26,3607.2 h150
  text "0.4mm" at 1022.99,3425.48 h100
  text "0.6mm" at 1572.99,3425.48 h100
  text "0.8mm" at 2122.99,3425.48 h100
  text "1.0mm" at 2672.99,3425.48 h100
  text "1.2mm" at 3222.99,3425.48 h100
  text "1.4mm" at 3772.99,3425.48 h100
  text "1.6mm" at 4322.99,3425.48 h100
  text "1.8mm" at 4872.99,3425.48 h100
  text "2.0mm" at 5422.99,3425.48 h100
  text "板厚" at 315.26,3406.98 h150
  text "1/2OZ" at 2252.99,3225.48 h100
  text "1OZ" at 2752.99,3225.48 h100
  text "2OZ" at 3252.99,3225.48 h100
  text "（完成铜厚）" at 1256.29,3212.73 h130
  text "外层" at 980.04,3206.48 h150
  text "铜厚" at 315.12,3205.2 h150
  text "白色" at 1472.99,3025.48 h100
  text "其他：" at 2172.99,3025.48 h100
  text "丝印颜色" at 315.12,3005.98 h150
  text "绿色" at 1472.99,2825.48 h100
  text "黑色" at 2172.99,2825.48 h100
  text "红色" at 2872.99,2825.48 h100
  text "蓝色" at 3572.99,2825.48 h100
  text "黄色" at 4272.99,2825.48 h100
  text "其他：" at 4972.99,2825.48 h100
  text "（亮光）" at 855.49,2812.88 h130
  text "阻焊颜色" at 315.12,2805.77 h150
  text "沉镍金" at 1472.99,2625.48 h100
  text "无铅喷锡" at 2172.99,2625.48 h100
  text "电镀镍金" at 2872.99,2625.48 h100
  text "电镀软金" at 3572.99,2625.48 h100
  text "化学沉锡" at 4272.99,2625.48 h100
  text "光板" at 4972.99,2625.48 h100
  text "OSP" at 5492.99,2625.48 h100
  text "表面处理工艺" at 315.12,2604.56 h150
  text "无" at 1472.99,2426.48 h100
  text "按键镀硬金" at 1892.99,2426.48 h100
  text "金手指" at 2612.99,2426.48 h100
  text "半孔工艺" at 3302.99,2426.48 h100
  text "FPCB补强" at 3992.99,2426.48 h100
  text "树脂塞孔" at 4682.99,2426.48 h100
  text "电镀填孔" at 5372.99,2426.48 h100
  text "特殊工艺" at 315.12,2405.34 h150
  text "是" at 1472.99,2225.48 h100
  text "否" at 2172.99,2225.48 h100
  text "按文件" at 2872.99,2225.48 h100
  text "是否阻焊塞孔" at 315.26,2204.7 h150
  text "非拼板" at 1472.99,2025.48 h100
  text "拼板" at 2172.99,2025.48 h100
  text "分成单板交货" at 2872.99,2025.48 h100
  text "交货方式" at 315.12,2005.48 h150
  text "Gerber输出：英制、相对零点、抑制前导零、精度2:5" at 317.99,1831.48 h120
  text "Ver 18.04.19" at 5012.99,1764.48 h120
  text "NC Drill输出：英制、相对零点、抑制前导零、精度2:4" at 317.99,1691.48 h120
  text "R" at 5363.99,1561.98 h25
  text "其他说明" at 312.99,1516.48 h150
  text "94V-0" at 5433.99,1506.48 h46
  text "标识样式>>>" at 4572.99,1451.48 h120
  text "CTI>=175" at 5277.99,1421.48 h86.61
  text "1." at 287.99,1381.48 h120
  text "机械1层(*.GM1)为外形铣边；若存在工艺副边，请在副边上增加分流点" at 412.99,1381.48 h120
  text "2." at 287.88,1251.48 h120
  text "请用供应商UL认证号，防火等级，CTI等级，生产周期替换放置在板上的UR标识，且保持其位置、方向一致；" at 412.99,1251.48 h120
  text "禁止添加板内不存在的标识，包括供应商LOGO、无铅等。但工艺副边不受限" at 412.99,1121.48 h120
  text "3." at 287.99,991.48 h120
  text "若焊盘开窗与丝印油冲突，焊盘处需将丝印油掏开，不允许上盘" at 412.99,991.48 h120
  text "4." at 287.99,871.48 h120
  text "若存在V-CUT，无特别说明时，须为双面V-CUT，角度30（+-5°），余量按以下表格执行" at 412.99,871.48 h120
  text "PCB厚度（mm）" at 843.99,696.48 h120
  text "筋厚" at 508.99,681.48 h120
  text "（余量）" at 458.99,561.48 h120
  text "0.6" at 843.99,556.48 h120
  text "0.8" at 1083.61,556.48 h120
  text "1" at 1379.92,556.48 h120
  text "1.2" at 1563.99,556.48 h120
  text "1.6" at 1803.99,556.48 h120
  text "2" at 2088.99,556.48 h120
  text "2.5" at 2283.39,556.48 h120
  text "3" at 2568.99,556.48 h120
  text "0.16" at 814.13,418.98 h120
  text "0.2" at 1084.13,418.98 h120
  text "0.3" at 1324.13,418.98 h120
  text "0.3" at 1559.99,418.98 h120
  text "0.4" at 1800.51,418.98 h120
  text "0.5" at 2044.28,418.98 h120
  text "0.5" at 2284.13,418.98 h120
  text "最小值" at 453.99,416.48 h120
  text "0.5" at 2522.99,416.48 h120
  text "0.32" at 814.53,281.48 h120
  text "0.4" at 1083.84,281.48 h120
  text "0.45" at 1293.98,281.48 h120
  text "0.5" at 1559.71,281.48 h120
  text "0.6" at 1802.99,281.48 h120
  text "0.7" at 2044.57,281.48 h120
  text "0.8" at 2284.3,281.48 h120
  text "0.8" at 2524.11,281.48 h120
  text "最大值" at 453.99,276.48 h120
  text "5." at 287.99,106.48 h120
  text "PCB做完后，请高温烘烤进行应力释放，再整平（或重物压板烘烤），防止翘曲" at 412.99,106.48 h120
  text "我司生产使用无铅工艺制程" at 407.99,-28.52 h120
  text "6." at 287.99,-33.52 h120
  text "7." at 287.99,-178.52 h120
  text "未尽事项请参照我司《PCB质量补充协议》" at 407.99,-178.52 h120
Mechanical 15:
  lines w6: -3936.95,196.85 0,196.85 ; -3936.95,2362.21 0,2362.21 ; -3740.16,196.85 -3740.16,2224.41
  lines w10: -3759.84,20.71 -3759.84,176.65 -3603.9,176.65 ; -3759.84,2225.43 -3759.84,2381.38 -3603.9,2381.38 ; -2083.5,176.65 -1927.56,176.65 -1927.56,332.59 ; -1929.13,2225.43 -1929.13,2381.37 -1773.19,2381.37 ; -333.11,176.65 -177.17,176.65 -177.17,332.59 ; -177.17,2225.43 -177.17,2381.37 -21.22,2381.37
Drill Drawing:
  text ".Legend" at 355,4560 h30

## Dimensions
-7952.76,-174.89 to 0,-175 on Mechanical 1
-8127.76,5118.17 to -8127.76,0.11 on Mechanical 1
